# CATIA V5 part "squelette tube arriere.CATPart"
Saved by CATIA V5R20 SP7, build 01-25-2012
Part number: squelette tube arriere
Publications: "hauteur du pivot plus haut", "longeur du tube", "hauteur du pivot plus bas", "position horizontale du pivot plus bas", "rayon interieur", "Plan.1", "Plan.2", "Plan.3", "Point.1", "Droite.1", "Point.2", "Droite.2", "Point.3", "Droite.3", "Droite.4", "epaisseur du pivot"
Bounding box of the stored display mesh (mm): x 0 to 50.01, y 0 to 40, z 0 to 375
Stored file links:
  D:\thinkmotion-MPB\Dropbox\Pack 1 sylvain\CFAO_2010_yyang\yyang\CFAO_2010_yyang\squelette tube arriere.CATPart
  D:\thinkmotion-MPB\Dropbox\Pack 1 sylvain\CFAO_2010_yyang\yyang\CFAO_2010_yyang\yyang.CATProduct
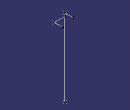
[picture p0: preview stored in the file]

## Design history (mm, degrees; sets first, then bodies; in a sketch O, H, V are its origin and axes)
Parameters
  `hauteur du pivot plus haut` = 375 mm {= `longeur du tube`+25mm}
  `longeur du tube` = 350 mm
  `hauteur du pivot plus bas` = 360 mm {= `longeur du tube`+`External.distance entre le haut et le pivot plus haut`}
  `position horizontale du pivot plus bas` = 50.01 mm {= `External.position verticale du pivot plus haut`+0.01mm}
  `rayon interieur` = 18 mm
  `epaisseur du pivot` = 2 mm
External parameters (linked from other documents)
  `External.distance entre le haut et le pivot plus haut` = 10 mm
  `External.position horizontale du pivot2` = 50 mm
  `External.position verticale du pivot plus haut` = 50 mm
Body1 (main body)
  Plane1: type Offset, RefPlane xy-plane, Offset 0
  Plane2: type Offset, RefPlane yz-plane, Offset 0
  Plane3: type Offset, RefPlane zx-plane, Offset 0
  Point1: (0, 0, 0)
  Line1: type PtDir, RefPoint Point1, Direction (0, 0, 1), Start 0, End 375 {= `hauteur du pivot plus haut`}
  Point2: (0, 0, 0), relative to vertex of Line1
  Line2: type PtDir, RefPoint Point2, Direction (0, 1, 0), Start 0, End 40
  Point3: (50.01 {= `position horizontale du pivot plus bas`}, 0, 360 {= `hauteur du pivot plus bas`})
  Line3: type PtDir, LineFirstUpto Line1, RefPoint Point3, Direction (1, 0, 0), Start 0, End 0
  Line4: type PtDir, RefPoint Point3, Direction (0, 1, 0), Start 0, End 40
